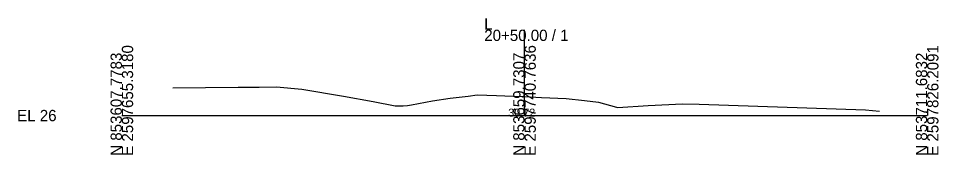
# Model space of a CAD drawing. Extents: x -26 to 1203, y -10 to 9526.
# Drawn here: x 974.3 to 1202.8, y 490.3 to 524.1 of the extents above; entities that cross this region are included whole.
import ezdxf

# ---------------------------------------------------------------- set-up
doc = ezdxf.new("R2010")
doc.units = 0
for name, color, linetype in [('Exist Cross Section Cell', 7, 'Continuous'), ('Exist XS Center Line Elevation Label', 7, 'Continuous'), ('Exist XS Ground Line', 7, 'Continuous')]:
    doc.layers.add(name, color=color, linetype=linetype)

msp = doc.modelspace()

# ---------------------------------------------------------------- linework, layer by layer
at = {"layer": 'Exist Cross Section Cell'}
for p, q in [((1100, 500), (1100, 521.31)), ((1000, 500), (1100, 500)), ((1100, 500), (1200, 500))]:
    msp.add_line(p, q, dxfattribs=at)
at = {"layer": 'Exist XS Ground Line'}
for p, q in [((1012.68, 506.85), (1028.9, 507.03)), ((1028.9, 507.03), (1034.13, 507.05)), ((1034.13, 507.05), (1038.41, 507.1)), ((1038.41, 507.1), (1044.67, 506.56)), ((1044.67, 506.56), (1055.08, 504.78)), ((1085.98, 504.83), (1088.27, 505.12)), ((1088.27, 505.12), (1093.08, 504.96)), ((1055.08, 504.78), (1062.45, 503.51)), ((1062.45, 503.51), (1067.85, 502.42)), ((1071.9, 502.63), (1077.18, 503.62)), ((1077.18, 503.62), (1081.5, 504.32)), ((1081.5, 504.32), (1085.98, 504.83)), ((1093.08, 504.96), (1099.34, 504.75)), ((1099.34, 504.75), (1100, 504.72)), ((1100, 504.72), (1104.21, 504.52)), ((1104.21, 504.52), (1110.32, 504.25)), ((1110.32, 504.25), (1114.93, 503.74)), ((1114.93, 503.74), (1118.39, 503.35)), ((1118.39, 503.35), (1122.84, 502.07)), ((1130.71, 502.52), (1139.23, 502.93)), ((1139.23, 502.93), (1143.41, 502.84)), ((1143.41, 502.84), (1184.69, 501.41)), ((1067.85, 502.42), (1069.84, 502.44)), ((1069.84, 502.44), (1070.93, 502.49)), ((1070.93, 502.49), (1071.9, 502.63)), ((1122.84, 502.07), (1123.16, 501.98)), ((1123.16, 501.98), (1130.71, 502.52)), ((1184.69, 501.41), (1188.14, 501.11))]:
    msp.add_line(p, q, dxfattribs=at)

# ---------------------------------------------------------------- texts
at = {"layer": 'Exist Cross Section Cell'}
for s, p in [('L', (1090, 521.31)), ('20+50.00 / 1', (1090, 518.51)), ('EL 26', (974, 498.6))]:
    msp.add_text(s, height=2.8, dxfattribs=at).set_placement(p)
for s, p in [('E 2597655.3180', (1002.8, 490)), ('E 2597740.7636', (1102.8, 490)), ('E 2597826.2091', (1202.8, 490)), ('N 853607.7783', (1000, 490)), ('N 853659.7307', (1100, 490)), ('N 853711.6832', (1200, 490))]:
    msp.add_text(s, height=2.8, rotation=90, dxfattribs=at).set_placement(p)
at = {"layer": 'Exist XS Center Line Elevation Label'}
msp.add_text('30.72', height=2, dxfattribs=at).set_placement((1095.96, 499.72))

doc.saveas('drawing.dxf')
